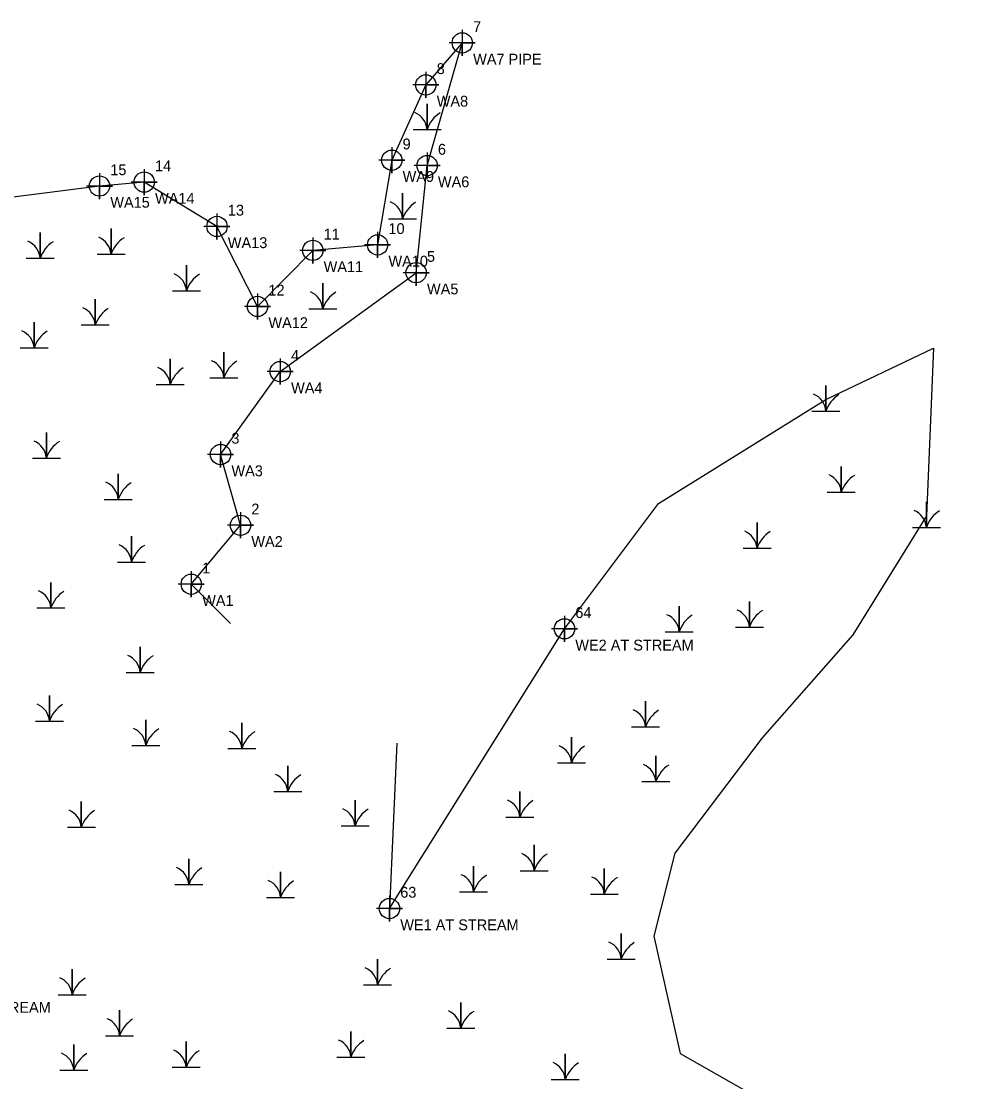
# Model space of a CAD drawing. Extents: x 2189822 to 2190837, y 387253 to 388663.
# Drawn here: x 2190334.4 to 2190555.2, y 387891.4 to 388135.9 of the extents above; entities that cross this region are included whole.
import ezdxf

# ---------------------------------------------------------------- set-up
doc = ezdxf.new("R2010")
doc.units = 0
for name, color, linetype in [('COGO Default Chain', 7, 'Continuous'), ('DTM Contours Major', 7, 'Continuous'), ('DTM Contours Minor', 7, 'Continuous'), ('Exist DTM Breakline Cogo Elevation', 7, 'Continuous'), ('Exist DTM Breakline Cogo Number', 7, 'Continuous')]:
    doc.layers.add(name, color=color, linetype=linetype)

msp = doc.modelspace()

# ---------------------------------------------------------------- linework, layer by layer
at = {"layer": 'DTM Contours Major'}
for points in [[(2190436.1, 388133.93), (2190436.1, 388127.93), (2190436.1, 388130.93), (2190439.1, 388130.93), (2190433.1, 388130.93)], [(2190427.71, 388124.24), (2190427.71, 388118.24), (2190427.71, 388121.24), (2190430.71, 388121.24), (2190424.71, 388121.24)], [(2190419.84, 388106.88), (2190419.84, 388100.88), (2190419.84, 388103.88), (2190422.84, 388103.88), (2190416.84, 388103.88)], [(2190427.98, 388105.65), (2190427.98, 388099.65), (2190427.98, 388102.65), (2190430.98, 388102.65), (2190424.98, 388102.65)], [(2190362.76, 388101.84), (2190362.76, 388095.84), (2190362.76, 388098.84), (2190365.76, 388098.84), (2190359.76, 388098.84)], [(2190352.44, 388100.93), (2190352.44, 388094.93), (2190352.44, 388097.93), (2190355.44, 388097.93), (2190349.44, 388097.93)], [(2190379.54, 388091.61), (2190379.54, 388085.61), (2190379.54, 388088.61), (2190382.54, 388088.61), (2190376.54, 388088.61)], [(2190416.58, 388087.36), (2190416.58, 388081.36), (2190416.58, 388084.36), (2190419.58, 388084.36), (2190413.58, 388084.36)], [(2190401.63, 388086.09), (2190401.63, 388080.09), (2190401.63, 388083.09), (2190404.63, 388083.09), (2190398.63, 388083.09)], [(2190425.46, 388080.95), (2190425.46, 388074.95), (2190425.46, 388077.95), (2190428.46, 388077.95), (2190422.46, 388077.95)], [(2190388.9, 388073.17), (2190388.9, 388067.17), (2190388.9, 388070.17), (2190391.9, 388070.17), (2190385.9, 388070.17)], [(2190394.13, 388058.14), (2190394.13, 388052.14), (2190394.13, 388055.14), (2190397.13, 388055.14), (2190391.13, 388055.14)], [(2190380.37, 388039.02), (2190380.37, 388033.02), (2190380.37, 388036.02), (2190383.37, 388036.02), (2190377.37, 388036.02)], [(2190384.96, 388022.7), (2190384.96, 388016.7), (2190384.96, 388019.7), (2190387.96, 388019.7), (2190381.96, 388019.7)], [(2190373.62, 388009.11), (2190373.62, 388003.11), (2190373.62, 388006.11), (2190376.62, 388006.11), (2190370.62, 388006.11)], [(2190459.66, 387998.83), (2190459.66, 387992.83), (2190459.66, 387995.83), (2190462.66, 387995.83), (2190456.66, 387995.83)], [(2190419.3, 387934.34), (2190419.3, 387928.34), (2190419.3, 387931.34), (2190422.3, 387931.34), (2190416.3, 387931.34)]]:
    msp.add_lwpolyline(points, dxfattribs=at)
for centre in [(2190436.1, 388130.93), (2190427.71, 388121.24), (2190419.84, 388103.88), (2190427.98, 388102.65), (2190352.44, 388097.93), (2190362.76, 388098.84), (2190379.54, 388088.61), (2190401.63, 388083.09), (2190416.58, 388084.36), (2190425.46, 388077.95), (2190388.9, 388070.17), (2190394.13, 388055.14), (2190380.37, 388036.02), (2190384.96, 388019.7), (2190373.62, 388006.11), (2190459.66, 387995.83), (2190419.3, 387931.34)]:
    msp.add_circle(centre, 2.34, dxfattribs=at)
at = {"layer": 'Exist DTM Breakline Cogo Elevation'}
for p, q in [((2190427.98, 388113.65), (2190427.98, 388113.65)), ((2190422.34, 388093.03), (2190422.34, 388093.03)), ((2190355.11, 388084.86), (2190355.11, 388084.86)), ((2190338.77, 388083.93), (2190338.77, 388083.93)), ((2190372.49, 388076.45), (2190372.49, 388076.45)), ((2190403.92, 388072.3), (2190403.92, 388072.3)), ((2190351.48, 388068.57), (2190351.48, 388068.57)), ((2190337.38, 388063.28), (2190337.38, 388063.28)), ((2190381.13, 388056.4), (2190381.13, 388056.4)), ((2190368.75, 388054.81), (2190368.75, 388054.81)), ((2190519.95, 388048.69), (2190519.95, 388048.69)), ((2190340.2, 388037.88), (2190340.2, 388037.88)), ((2190356.76, 388028.36), (2190356.76, 388028.36)), ((2190523.5, 388030.04), (2190523.5, 388030.04)), ((2190543.11, 388021.88), (2190543.11, 388021.88)), ((2190504.06, 388017.08), (2190504.06, 388017.08)), ((2190359.83, 388013.92), (2190359.83, 388013.92)), ((2190341.25, 388003.31), (2190341.25, 388003.31)), ((2190502.32, 387998.92), (2190502.32, 387998.92)), ((2190502.32, 387998.92), (2190502.32, 387998.92)), ((2190486.12, 387997.84), (2190486.12, 387997.84)), ((2190361.81, 387988.46), (2190361.81, 387988.46)), ((2190340.9, 387977.21), (2190340.9, 387977.21)), ((2190478.36, 387975.9), (2190478.36, 387975.9)), ((2190363.13, 387971.6), (2190363.13, 387971.6)), ((2190385.27, 387970.94), (2190385.27, 387970.94)), ((2190461.29, 387967.59), (2190461.29, 387967.59)), ((2190480.73, 387963.27), (2190480.73, 387963.27)), ((2190395.85, 387961.02), (2190395.85, 387961.02)), ((2190449.38, 387955.07), (2190449.38, 387955.07)), ((2190348.26, 387952.75), (2190348.26, 387952.75)), ((2190411.38, 387953.08), (2190411.38, 387953.08)), ((2190452.66, 387942.75), (2190452.66, 387942.75)), ((2190373.05, 387939.53), (2190373.05, 387939.53)), ((2190438.71, 387937.88), (2190438.71, 387937.88)), ((2190394.19, 387936.55), (2190394.19, 387936.55)), ((2190468.85, 387937.34), (2190468.85, 387937.34)), ((2190468.85, 387937.34), (2190468.85, 387937.34)), ((2190472.75, 387922.34), (2190472.75, 387922.34)), ((2190416.57, 387916.38), (2190416.57, 387916.38)), ((2190346.14, 387914.13), (2190346.14, 387914.13)), ((2190435.74, 387906.47), (2190435.74, 387906.47)), ((2190357.09, 387904.69), (2190357.09, 387904.69)), ((2190410.41, 387899.76), (2190410.41, 387899.76)), ((2190346.51, 387896.75), (2190346.51, 387896.75)), ((2190372.43, 387897.41), (2190372.43, 387897.41)), ((2190459.86, 387894.56), (2190459.86, 387894.56))]:
    msp.add_line(p, q, dxfattribs=at)
for points in [[(2190424.75, 388110.98), (2190427.98, 388110.98), (2190427.98, 388116.89), (2190427.98, 388110.98), (2190431.2, 388110.98)], [(2190419.11, 388090.36), (2190422.34, 388090.36), (2190422.34, 388096.28), (2190422.34, 388090.36), (2190425.56, 388090.36)], [(2190335.54, 388081.26), (2190338.77, 388081.26), (2190338.77, 388087.18), (2190338.77, 388081.26), (2190341.99, 388081.26)], [(2190351.89, 388082.18), (2190355.11, 388082.18), (2190355.11, 388088.1), (2190355.11, 388082.18), (2190358.34, 388082.18)], [(2190369.27, 388073.77), (2190372.5, 388073.77), (2190372.5, 388079.69), (2190372.5, 388073.77), (2190375.72, 388073.77)], [(2190400.7, 388069.63), (2190403.92, 388069.63), (2190403.92, 388075.54), (2190403.92, 388069.63), (2190407.15, 388069.63)], [(2190348.25, 388065.9), (2190351.48, 388065.9), (2190351.48, 388071.81), (2190351.48, 388065.9), (2190354.7, 388065.9)], [(2190334.15, 388060.6), (2190337.38, 388060.6), (2190337.38, 388066.52), (2190337.38, 388060.6), (2190340.6, 388060.6)], [(2190365.53, 388052.14), (2190368.75, 388052.14), (2190368.75, 388058.06), (2190368.75, 388052.14), (2190371.98, 388052.14)], [(2190377.9, 388053.73), (2190381.13, 388053.73), (2190381.13, 388059.65), (2190381.13, 388053.73), (2190384.35, 388053.73)], [(2190516.72, 388046.02), (2190519.95, 388046.02), (2190519.95, 388051.94), (2190519.95, 388046.02), (2190523.17, 388046.02)], [(2190336.97, 388035.21), (2190340.2, 388035.21), (2190340.2, 388041.12), (2190340.2, 388035.21), (2190343.42, 388035.21)], [(2190520.27, 388027.37), (2190523.5, 388027.37), (2190523.5, 388033.29), (2190523.5, 388027.37), (2190526.72, 388027.37)], [(2190353.54, 388025.68), (2190356.77, 388025.68), (2190356.77, 388031.6), (2190356.77, 388025.68), (2190359.99, 388025.68)], [(2190539.89, 388019.21), (2190543.11, 388019.21), (2190543.11, 388025.13), (2190543.11, 388019.21), (2190546.34, 388019.21)], [(2190500.84, 388014.41), (2190504.06, 388014.41), (2190504.06, 388020.32), (2190504.06, 388014.41), (2190507.29, 388014.41)], [(2190356.6, 388011.24), (2190359.83, 388011.24), (2190359.83, 388017.16), (2190359.83, 388011.24), (2190363.05, 388011.24)], [(2190338.03, 388000.64), (2190341.25, 388000.64), (2190341.25, 388006.55), (2190341.25, 388000.64), (2190344.48, 388000.64)], [(2190499.09, 387996.25), (2190502.32, 387996.25), (2190502.32, 388002.16), (2190502.32, 387996.25), (2190505.54, 387996.25)], [(2190499.09, 387996.25), (2190502.32, 387996.25), (2190502.32, 388002.16), (2190502.32, 387996.25), (2190505.54, 387996.25)], [(2190482.9, 387995.17), (2190486.13, 387995.17), (2190486.13, 388001.08), (2190486.13, 387995.17), (2190489.35, 387995.17)], [(2190358.59, 387985.79), (2190361.81, 387985.79), (2190361.81, 387991.7), (2190361.81, 387985.79), (2190365.04, 387985.79)], [(2190337.68, 387974.53), (2190340.9, 387974.53), (2190340.9, 387980.45), (2190340.9, 387974.53), (2190344.13, 387974.53)], [(2190475.14, 387973.22), (2190478.36, 387973.22), (2190478.36, 387979.14), (2190478.36, 387973.22), (2190481.59, 387973.22)], [(2190359.91, 387968.92), (2190363.13, 387968.92), (2190363.13, 387974.84), (2190363.13, 387968.92), (2190366.36, 387968.92)], [(2190382.05, 387968.26), (2190385.27, 387968.26), (2190385.27, 387974.18), (2190385.27, 387968.26), (2190388.5, 387968.26)], [(2190458.07, 387964.92), (2190461.29, 387964.92), (2190461.29, 387970.84), (2190461.29, 387964.92), (2190464.52, 387964.92)], [(2190477.5, 387960.6), (2190480.73, 387960.6), (2190480.73, 387966.51), (2190480.73, 387960.6), (2190483.95, 387960.6)], [(2190392.62, 387958.34), (2190395.85, 387958.34), (2190395.85, 387964.26), (2190395.85, 387958.34), (2190399.07, 387958.34)], [(2190446.15, 387952.39), (2190449.38, 387952.39), (2190449.38, 387958.31), (2190449.38, 387952.39), (2190452.61, 387952.39)], [(2190345.04, 387950.08), (2190348.26, 387950.08), (2190348.26, 387956), (2190348.26, 387950.08), (2190351.49, 387950.08)], [(2190408.15, 387950.41), (2190411.38, 387950.41), (2190411.38, 387956.33), (2190411.38, 387950.41), (2190414.6, 387950.41)], [(2190449.43, 387940.07), (2190452.66, 387940.07), (2190452.66, 387945.99), (2190452.66, 387940.07), (2190455.88, 387940.07)], [(2190369.82, 387936.85), (2190373.05, 387936.85), (2190373.05, 387942.77), (2190373.05, 387936.85), (2190376.27, 387936.85)], [(2190435.48, 387935.2), (2190438.71, 387935.2), (2190438.71, 387941.12), (2190438.71, 387935.2), (2190441.94, 387935.2)], [(2190465.63, 387934.67), (2190468.85, 387934.67), (2190468.85, 387940.59), (2190468.85, 387934.67), (2190472.08, 387934.67)], [(2190465.63, 387934.67), (2190468.85, 387934.67), (2190468.85, 387940.59), (2190468.85, 387934.67), (2190472.08, 387934.67)], [(2190390.97, 387933.88), (2190394.2, 387933.88), (2190394.2, 387939.8), (2190394.2, 387933.88), (2190397.42, 387933.88)], [(2190469.52, 387919.66), (2190472.75, 387919.66), (2190472.75, 387925.58), (2190472.75, 387919.66), (2190475.97, 387919.66)], [(2190413.34, 387913.71), (2190416.57, 387913.71), (2190416.57, 387919.63), (2190416.57, 387913.71), (2190419.8, 387913.71)], [(2190342.91, 387911.46), (2190346.14, 387911.46), (2190346.14, 387917.38), (2190346.14, 387911.46), (2190349.36, 387911.46)], [(2190432.51, 387903.79), (2190435.74, 387903.79), (2190435.74, 387909.71), (2190435.74, 387903.79), (2190438.96, 387903.79)], [(2190353.86, 387902.01), (2190357.09, 387902.01), (2190357.09, 387907.93), (2190357.09, 387902.01), (2190360.31, 387902.01)], [(2190407.18, 387897.08), (2190410.41, 387897.08), (2190410.41, 387903), (2190410.41, 387897.08), (2190413.63, 387897.08)], [(2190343.29, 387894.08), (2190346.51, 387894.08), (2190346.51, 387899.99), (2190346.51, 387894.08), (2190349.74, 387894.08)], [(2190369.21, 387894.74), (2190372.43, 387894.74), (2190372.43, 387900.65), (2190372.43, 387894.74), (2190375.66, 387894.74)], [(2190456.63, 387891.89), (2190459.86, 387891.89), (2190459.86, 387897.81), (2190459.86, 387891.89), (2190463.08, 387891.89)]]:
    msp.add_lwpolyline(points, dxfattribs=at)
for centre, radius, start, end in [((2190423.38, 388110.64), 4.61, 4.1403, 67.535), ((2190434.82, 388108.7), 7.21, 122.1274, 161.6222), ((2190417.74, 388090.03), 4.61, 4.1403, 67.535), ((2190429.18, 388088.09), 7.21, 122.1274, 161.6222), ((2190334.17, 388080.93), 4.61, 4.1403, 67.535), ((2190345.61, 388078.99), 7.21, 122.1274, 161.6222), ((2190350.51, 388081.85), 4.61, 4.1403, 67.535), ((2190361.95, 388079.91), 7.21, 122.1274, 161.6222), ((2190367.9, 388073.44), 4.61, 4.1403, 67.535), ((2190379.34, 388071.5), 7.21, 122.1274, 161.6222), ((2190399.32, 388069.29), 4.61, 4.1403, 67.535), ((2190410.76, 388067.35), 7.21, 122.1274, 161.6222), ((2190346.88, 388065.56), 4.61, 4.1403, 67.535), ((2190358.32, 388063.62), 7.21, 122.1274, 161.6222), ((2190332.78, 388060.27), 4.61, 4.1403, 67.535), ((2190344.22, 388058.33), 7.21, 122.1274, 161.6222), ((2190376.53, 388053.4), 4.61, 4.1403, 67.535), ((2190387.97, 388051.46), 7.21, 122.1274, 161.6222), ((2190364.15, 388051.8), 4.61, 4.1403, 67.535), ((2190375.59, 388049.87), 7.21, 122.1274, 161.6222), ((2190515.35, 388045.68), 4.61, 4.1403, 67.535), ((2190526.79, 388043.74), 7.21, 122.1274, 161.6222), ((2190335.6, 388034.87), 4.61, 4.1403, 67.535), ((2190347.04, 388032.93), 7.21, 122.1274, 161.6222), ((2190518.9, 388027.04), 4.61, 4.1403, 67.535), ((2190530.34, 388025.1), 7.21, 122.1274, 161.6222), ((2190352.17, 388025.35), 4.61, 4.1403, 67.535), ((2190363.61, 388023.41), 7.21, 122.1274, 161.6222), ((2190538.51, 388018.88), 4.61, 4.1403, 67.535), ((2190549.96, 388016.94), 7.21, 122.1274, 161.6222), ((2190499.46, 388014.07), 4.61, 4.1403, 67.535), ((2190510.9, 388012.13), 7.21, 122.1274, 161.6222), ((2190355.23, 388010.91), 4.61, 4.1403, 67.535), ((2190366.67, 388008.97), 7.21, 122.1274, 161.6222), ((2190336.65, 388000.3), 4.61, 4.1403, 67.535), ((2190348.09, 387998.36), 7.21, 122.1274, 161.6222), ((2190481.53, 387994.83), 4.61, 4.1403, 67.535), ((2190492.97, 387992.89), 7.21, 122.1274, 161.6222), ((2190497.72, 387995.91), 4.61, 4.1403, 67.535), ((2190497.72, 387995.91), 4.61, 4.1403, 67.535), ((2190509.16, 387993.97), 7.21, 122.1274, 161.6222), ((2190509.16, 387993.97), 7.21, 122.1274, 161.6222), ((2190357.21, 387985.45), 4.61, 4.1403, 67.535), ((2190368.65, 387983.51), 7.21, 122.1274, 161.6222), ((2190336.3, 387974.2), 4.61, 4.1403, 67.535), ((2190347.74, 387972.26), 7.21, 122.1274, 161.6222), ((2190473.76, 387972.89), 4.61, 4.1403, 67.535), ((2190485.2, 387970.95), 7.21, 122.1274, 161.6222), ((2190358.53, 387968.59), 4.61, 4.1403, 67.535), ((2190369.97, 387966.65), 7.21, 122.1274, 161.6222), ((2190380.67, 387967.93), 4.61, 4.1403, 67.535), ((2190392.11, 387965.99), 7.21, 122.1274, 161.6222), ((2190456.69, 387964.59), 4.61, 4.1403, 67.535), ((2190468.13, 387962.65), 7.21, 122.1274, 161.6222), ((2190476.13, 387960.26), 4.61, 4.1403, 67.535), ((2190391.25, 387958.01), 4.61, 4.1403, 67.535), ((2190402.69, 387956.07), 7.21, 122.1274, 161.6222), ((2190487.57, 387958.32), 7.21, 122.1274, 161.6222), ((2190444.78, 387952.06), 4.61, 4.1403, 67.535), ((2190456.22, 387950.12), 7.21, 122.1274, 161.6222), ((2190343.66, 387949.75), 4.61, 4.1403, 67.535), ((2190355.1, 387947.81), 7.21, 122.1274, 161.6222), ((2190406.78, 387950.08), 4.61, 4.1403, 67.535), ((2190418.22, 387948.14), 7.21, 122.1274, 161.6222), ((2190448.06, 387939.74), 4.61, 4.1403, 67.535), ((2190459.5, 387937.8), 7.21, 122.1274, 161.6222), ((2190368.45, 387936.52), 4.61, 4.1403, 67.535), ((2190379.89, 387934.58), 7.21, 122.1274, 161.6222), ((2190389.6, 387933.55), 4.61, 4.1403, 67.535), ((2190401.04, 387931.61), 7.21, 122.1274, 161.6222), ((2190434.11, 387934.87), 4.61, 4.1403, 67.535), ((2190445.55, 387932.93), 7.21, 122.1274, 161.6222), ((2190464.25, 387934.34), 4.61, 4.1403, 67.535), ((2190464.25, 387934.34), 4.61, 4.1403, 67.535), ((2190475.69, 387932.4), 7.21, 122.1274, 161.6222), ((2190475.69, 387932.4), 7.21, 122.1274, 161.6222), ((2190468.15, 387919.33), 4.61, 4.1403, 67.535), ((2190479.59, 387917.39), 7.21, 122.1274, 161.6222), ((2190411.97, 387913.38), 4.61, 4.1403, 67.535), ((2190423.41, 387911.44), 7.21, 122.1274, 161.6222), ((2190341.54, 387911.12), 4.61, 4.1403, 67.535), ((2190352.98, 387909.18), 7.21, 122.1274, 161.6222), ((2190352.49, 387901.68), 4.61, 4.1403, 67.535), ((2190363.93, 387899.74), 7.21, 122.1274, 161.6222), ((2190431.14, 387903.46), 4.61, 4.1403, 67.535), ((2190442.58, 387901.52), 7.21, 122.1274, 161.6222), ((2190405.81, 387896.75), 4.61, 4.1403, 67.535), ((2190417.25, 387894.81), 7.21, 122.1274, 161.6222), ((2190367.83, 387894.4), 4.61, 4.1403, 67.535), ((2190379.27, 387892.46), 7.21, 122.1274, 161.6222), ((2190341.92, 387893.74), 4.61, 4.1403, 67.535), ((2190353.36, 387891.8), 7.21, 122.1274, 161.6222), ((2190455.26, 387891.56), 4.61, 4.1403, 67.535), ((2190466.7, 387889.62), 7.21, 122.1274, 161.6222)]:
    msp.add_arc(centre, radius, start, end, dxfattribs=at)
at = {"layer": 'Exist DTM Breakline Cogo Number'}
for p, q in [((2190373.62, 388006.11), (2190382.62, 387997.09)), ((2190420.98, 387969.45), (2190419.3, 387931.34)), ((2190486.31, 387897.92), (2190555.2, 387858.91))]:
    msp.add_line(p, q, dxfattribs=at)
for points in [[(2190373.62, 388006.11), (2190384.96, 388019.7), (2190380.37, 388036.02), (2190394.13, 388055.14), (2190425.46, 388077.95), (2190427.98, 388102.65), (2190436.1, 388130.93), (2190427.71, 388121.24), (2190419.84, 388103.88), (2190416.58, 388084.36), (2190401.63, 388083.09), (2190388.9, 388070.17), (2190379.54, 388088.61), (2190362.76, 388098.84), (2190352.44, 388097.93), (2190319.2, 388093.69)], [(2190459.66, 387995.83), (2190481.36, 388024.7), (2190519.95, 388048.69), (2190544.73, 388060.58), (2190543.11, 388021.88), (2190526.19, 387994.47), (2190505.24, 387970.68), (2190485.1, 387944.08), (2190480.26, 387924.93), (2190486.31, 387897.92)], [(2190419.3, 387931.34), (2190459.66, 387995.83)]]:
    msp.add_lwpolyline(points, dxfattribs=at)

# ---------------------------------------------------------------- texts
at = {"layer": 'COGO Default Chain'}
for s, p in [('WA7 PIPE', (2190438.6, 388125.93)), ('WA8', (2190430.21, 388116.24)), ('WA9', (2190422.34, 388098.88)), ('WA6', (2190430.48, 388097.65)), ('WA15', (2190354.94, 388092.93)), ('WA14', (2190365.26, 388093.84)), ('WA13', (2190382.04, 388083.61)), ('WA10', (2190419.08, 388079.36)), ('WA11', (2190404.13, 388078.09)), ('WA5', (2190427.96, 388072.95)), ('WA12', (2190391.4, 388065.17)), ('WA4', (2190396.63, 388050.14)), ('WA3', (2190382.87, 388031.02)), ('WA2', (2190387.46, 388014.7)), ('WA1', (2190376.12, 388001.11)), ('WE2 AT STREAM', (2190462.16, 387990.83)), ('WE1 AT STREAM', (2190421.8, 387926.34)), ('WF1 AT STREAM', (2190314.1, 387907.32))]:
    msp.add_text(s, height=2.5, dxfattribs=at).set_placement(p)
at = {"layer": 'DTM Contours Minor'}
for s, p in [('7', (2190438.6, 388133.43)), ('8', (2190430.21, 388123.74)), ('9', (2190422.34, 388106.38)), ('6', (2190430.48, 388105.15)), ('14', (2190365.26, 388101.34)), ('15', (2190354.94, 388100.43)), ('13', (2190382.04, 388091.11)), ('10', (2190419.08, 388086.86)), ('11', (2190404.13, 388085.59)), ('5', (2190427.96, 388080.45)), ('12', (2190391.4, 388072.67)), ('4', (2190396.63, 388057.64)), ('3', (2190382.87, 388038.52)), ('2', (2190387.46, 388022.2)), ('1', (2190376.12, 388008.61)), ('64', (2190462.16, 387998.33)), ('63', (2190421.8, 387933.84))]:
    msp.add_text(s, height=2.5, dxfattribs=at).set_placement(p)

doc.saveas('drawing.dxf')
